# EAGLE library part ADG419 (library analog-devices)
LC²MOS Precision Mini-DIP Analog switch Source: http://www.analog.com/UploadedFiles/Data_Sheets/ADG419.pdf
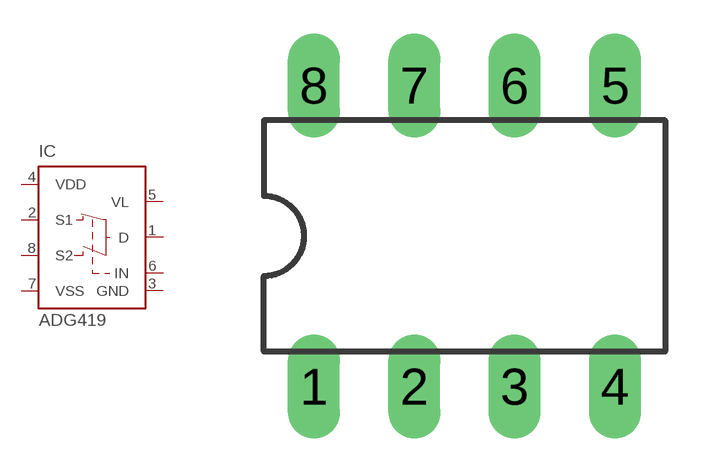
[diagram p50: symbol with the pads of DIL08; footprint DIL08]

Designator prefix IC

## ADG419 (MF: ALTERA CORPORATION; MPN: ADG419BN; OC_FARNELL: 1438705; OC_NEWARK: 16F6524)  [DIL08]
1  D
2  S1
3  GND  pwr
4  VDD  pwr
5  VL  pwr
6  IN  in
7  VSS  pwr
8  S2

## Footprint DIL08 (pad centres in mm)
Dual In Line Package
drill 0.813 long: 1 -3.81,-3.81; 2 -1.27,-3.81; 3 1.27,-3.81; 4 3.81,-3.81; 5 3.81,3.81; 6 1.27,3.81; 7 -1.27,3.81; 8 -3.81,3.81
